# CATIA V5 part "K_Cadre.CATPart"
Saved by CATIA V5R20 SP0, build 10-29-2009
Part number: Cadre
Bounding box of the stored display mesh (mm): x 0 to 570, y 94.924 to 274.924, z -110 to 712.271
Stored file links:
  G:\Khaled_CFAO_2011\ST2M\ST2M_GR1\bmartinez\Khaled\CAD_ThinkMOTION\K_Cadre.CATPart
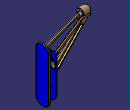
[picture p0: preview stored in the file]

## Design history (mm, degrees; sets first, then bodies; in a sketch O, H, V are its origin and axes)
Body1 (main body)
  Sketch1 on yz-plane, origin (0, 0, 0), H (0, 1, 0), V (0, 0, 1)
    arc A1 centre (187.8381, 667.2714) radius 45 from (227.6929, 646.3767) to (147.9989, 646.3467) ccw
    line L1 (147.9989, 646.3467) -> (110.2498, 449.9415)
    line L2 (110.2498, 449.9415) -> (110.2498, -0.0585)
    arc A2 centre (187.9199, -0.0585) radius 77.6701 from (110.2498, -0.0585) to (265.5899, 0) ccw
    point P5 (265.5899, 0)
    line L3 (265.5899, 0) -> (265.5899, 450)
    line L4 (265.5899, 450) -> (227.6929, 646.3767)
    radius A1 = 45
    distance A1 A2 = 700
    length L3 = 450
    length L2 = 450
    length L4 = 200
    length L1 = 200
    vertical: L2 V, L3 V
    coincidence: P5 H
    tangency: A2 L2
  Pad1: profile Sketch1, direction (1, 0, 0), length 1000
  Sketch2 on zx-plane, origin (0, 0, 0), H (-1, 0, 0), V (0, 0, 1)
    line L1 (40.1591, 586.4466) -> (-1.6835, 586.4466)
    line L2 (-1.6835, 586.4466) -> (-431.6835, -83.5534)
    line L3 (-431.6835, -83.5534) -> (70.1591, -83.5534)
    line L4 (70.1591, -83.5534) -> (40.1591, 586.4466)
    horizontal: L1 H, L3 H
  Pocket1: profile Sketch2, direction (0, -1, 0), length 1000, mirrored extent
  Sketch3 on zx-plane, origin (0, 0, 0), H (-1, 0, 0), V (0, 0, 1)
    line L1 (-100, 740) -> (-100, 650)
    line L2 (-100, 650) -> (-500, 450)
    line L3 (-500, 450) -> (-500, -110)
    line L4 (-500, -110) -> (-1040, -110)
    line L5 (-1040, -110) -> (-1040, 740)
    line L6 (-1040, 740) -> (-100, 740)
    vertical: L1 V, L3 V, L5 V
    horizontal: L4 H, L6 H
  Pocket2: profile Sketch3, direction (0, -1, 0), length 1000, mirrored extent
  Sketch4 on zx-plane, origin (0, 0, 0), H (-1, 0, 0), V (0, 0, 1)
    line L1 (-100, 610) -> (-460, 420)
    line L2 (-460, 420) -> (-460, 250)
    line L3 (-460, 250) -> (-100, 610)
    vertical: L2 V
  Pocket3: profile Sketch4, direction (0, -1, 0), length 1000, mirrored extent
  Sketch5 on zx-plane, origin (0, 0, 0), H (-1, 0, 0), V (0, 0, 1)
    point P1 (0, 600)
    line L1 (0, 600) -> (-450, 130)
    line L2 (-450, 130) -> (-450, -70)
    line L3 (-450, -70) -> (0, -70)
    point P4 (0, -70)
    line L4 (0, -70) -> (0, 600)
    coincidence: P1 V, P4 V
    vertical: L2 V, L4 V
    horizontal: L3 H
  Pocket4: profile Sketch5, direction (0, -1, 0), length 1000, mirrored extent
  Sketch6 on face of Pad1 from Sketch1.L3, origin (0, 265.5899, 0), H (-1, 0, 0), V (0, 0, 1)
    line L1 (-100.3985, 609.6245) -> (0, 609.6245)
    point P2 (0, 609.6245)
    line L2 (0, 609.6245) -> (0, -70)
    line L3 (0, -70) -> (-440, -70)
    line L4 (-440, -70) -> (-460.1088, -70)
    line L5 (-460.1088, -70) -> (-460.1088, 259.8942)
    line L6 (-460.1088, 259.8942) -> (-100.3985, 609.6245)
    coincidence: P2 V
    horizontal: L1 H, L3 H, L4 H
    vertical: L2 V, L5 V
  Pocket5: profile Sketch6, direction (0, -1, 0), length 55
  Sketch7 on face of Pad1 from Sketch1.L2, origin (0, 110.2498, 0), H (1, 0, 0), V (0, 0, 1)
    line L1 (100, 610) -> (460, 250)
    line L2 (460, 250) -> (460, -70)
    line L3 (460, -70) -> (0, -70)
    point P4 (0, -70)
    line L4 (0, -70) -> (0, 610)
    line L5 (0, 610) -> (100, 610)
    vertical: L2 V, L4 V
    coincidence: P4 V
    horizontal: L3 H, L5 H
  Pocket6: profile Sketch7, direction (0, 1, 0), length 55
  Sketch8 on end face of Pocket5, origin (0, 210.5899, 0), H (-1, 0, 0), V (0, 0, 1)
    line L1 (-450, 130) -> (-460, 130)
    line L2 (-460, 130) -> (-460, -100)
    line L3 (-460, -100) -> (-400, -100)
    line L4 (-400, -100) -> (-400, 130)
    line L5 (-400, 130) -> (-450, 130)
    horizontal: L1 H, L3 H, L5 H
    vertical: L2 V, L4 V
  Pocket7: profile Sketch8, direction (0, 1, 0), length 1000, mirrored extent
  Fillet1: radius 15, on edge [end face of Pocket5 | face of Pocket4 from Sketch5.L1]; edge [end face of Pocket5 | face of Pocket3 from Sketch4.L3]; edge [face of Pocket4 from Sketch5.L1 | end face of Pocket6]; edge [face of Pocket3 from Sketch4.L3 | end face of Pocket6]
  Sketch9 on face of Pocket2 from Sketch3.L2, origin (280, 0, 560), H (0, 1, 0), V (-0.8944, 0, 0.4472)
    line L1 (171.5802, 200) -> (199.1817, 200)
    line L2 (199.1817, 200) -> (235.4293, -220)
    line L3 (235.4293, -220) -> (135.4792, -220)
    line L4 (135.4792, -220) -> (171.5802, 200)
    reference projected line E1 (265.5899, -245.9675) -> (227.6929, 193.1442) from edge [face of Pad1 from Sketch1.L4 | face of Pocket2 from Sketch3.L2]
    reference projected line E2 (147.9989, 193.0772) -> (110.261, -245.9675) from edge [face of Pad1 from Sketch1.L1 | face of Pocket2 from Sketch3.L2]
    horizontal: L1 H, L3 H
    parallelism: L2 E1, L4 E2
  Pocket8: profile Sketch9, direction (0.4472, 0, 0.8944), length 45, mirrored extent
  Fillet2: radius 15, on edge [face of Pad1 from Sketch1.L4 | face of Pocket5 from Sketch6.L1]; edge [face of Pocket6 from Sketch7.L5 | face of Pad1 from Sketch1.L1]
  Sketch10 on start face of Pad1, origin (0, 0, 0), H (0, -1, 0), V (0, 0, 1)
    circle A1 centre (-187.8381, 667.2714) radius 25.1
    reference projected arc E1 centre (-187.8381, 667.2714) radius 45 from (-147.9989, 646.3467) to (-227.6929, 646.3767) ccw from edge [start face of Pad1 | face of Pad1 from Sketch1.A1]
    radius A1 = 25.1
    concentricity: A1 E1
  Pocket9: profile Sketch10, direction (1, 0, 0), length 500, mirrored extent
  Sketch11 on face of Pad1 from Sketch1.L2, origin (0, 110.2498, 0), H (1, 0, 0), V (0, 0, 1)
    line L1 (480, 470) -> (480, -110)
    line L2 (480, -110) -> (520, -110)
    line L3 (520, -110) -> (520, 470)
    line L4 (520, 470) -> (480, 470)
    vertical: L1 V, L3 V
    horizontal: L2 H, L4 H
  Pocket10: profile Sketch11, direction (0, 1, 0), length 200
  Fillet3: radius 6, on edge [face of Pad1 from Sketch1.L2 | face of Pocket7]; edge [face of Pad1 from Sketch1.A2 | face of Pocket7]; edge [face of Pocket5 from Sketch6.L5 | face of Pad1 from Sketch1.A2]; edge [face of Pad1 from Sketch1.L3 | face of Pocket5 from Sketch6.L5]; edge [face of Pad1 from Sketch1.L3 | face of Pocket7]
  Fillet4: radius 10, on edge [face of Pocket7 from Sketch8.L1 | face of Pocket4 from Sketch5.L1]; edge [face of Pocket7 from Sketch8.L1 | face of Fillet1] (x2)
  Fillet5: radius 12, on edge [face of Pad1 from Sketch1.L4 | face of Pocket2 from Sketch3.L2]; edge [face of Pad1 from Sketch1.L4 | face of Pocket3 from Sketch4.L1]; edge [face of Pocket3 from Sketch4.L1 | face of Pocket8 from Sketch9.L2]; edge [face of Pocket8 from Sketch9.L2 | face of Pocket2 from Sketch3.L2]; edge [face of Pocket8 from Sketch9.L4 | face of Pocket2 from Sketch3.L2]; edge [face of Pad1 from Sketch1.L1 | face of Pocket2 from Sketch3.L2]; edge [face of Pad1 from Sketch1.L1 | face of Pocket3 from Sketch4.L1]; edge [face of Pocket8 from Sketch9.L4 | face of Pocket3 from Sketch4.L1]
  Fillet6: radius 5, on edge [face of Pocket2 from Sketch3.L2 | face of Pocket8 from Sketch9.L3]
  Fillet7: radius 5, on edge [face of Pad1 from Sketch1.L2 | face of Fillet5]
  Fillet8: radius 5, on edge [face of Pad1 from Sketch1.L3 | face of Fillet5]
  Sketch12 on end face of Pocket6, origin (0, 165.2498, 0), H (1, 0, 0), V (0, 0, 1)
    construction line L1 (100, 550) -> (400, 240)
    line L2 (110.1626, 559.8347) -> (410.1626, 249.8347)
    line L3 (389.8374, 230.1653) -> (89.8374, 540.1653)
    arc A1 centre (400, 240) radius 14.1421 from (410.1626, 249.8347) to (389.8374, 230.1653) cw
    arc A2 centre (100, 550) radius 14.1421 from (89.8374, 540.1653) to (110.1626, 559.8347) cw
    distance L1 L2 = 14.1421
    tangency: A1 L2, A2 L2, A1 L3, A2 L3
  Pocket11: profile Sketch12, direction (0, -1, 0), length 500, mirrored extent
  Sketch13 on face of Pocket10 from Sketch11.L1, origin (480, 0, 0), H (0, 1, 0), V (0, 0, 1)
    circle A1 centre (148.2498, 380) radius 15
    point P1 (148.2498, 380)
    circle A2 centre (227.5899, 380) radius 15
    point P2 (227.5899, 380)
    circle A3 centre (187.9199, 65.4333) radius 25
    point P3 (187.9199, 65.4333)
    reference projected line E1 (112.183, 460) -> (263.6601, 460) from edge [face of Pocket10 from Sketch11.L1 | face of Pocket2 from Sketch3.L2]
    reference projected line E2 (112.183, 460) -> (263.6601, 460) from edge [face of Pocket10 from Sketch11.L1 | face of Pocket2 from Sketch3.L2]
    reference projected line E3 (265.5899, 0) -> (265.5899, 450) from edge [face of Pad1 from Sketch1.L3 | face of Pocket10 from Sketch11.L1]
    reference projected line E4 (110.2498, 449.9415) -> (110.2498, -0.0585) from edge [face of Pad1 from Sketch1.L2 | face of Pocket10 from Sketch11.L1]
    reference projected line E5 (110.2498, 449.9415) -> (110.2498, -0.0585) from edge [face of Pad1 from Sketch1.L2 | face of Pocket10 from Sketch11.L1]
    reference projected line E6 (265.5899, 0) -> (265.5899, 450) from edge [face of Pad1 from Sketch1.L3 | face of Pocket10 from Sketch11.L1]
    reference projected line E7 (265.5899, 0) -> (265.5899, 450) from edge [face of Pad1 from Sketch1.L3 | face of Pocket10 from Sketch11.L1]
    radius A3 = 25
    radius A2 = 15
    radius A1 = 15
    distance P1 E1 = 80
    distance P2 E2 = 80
    distance P2 E3 = 38
    distance E4 P1 = 38
    distance E5 E6 = 155.3402 (reference)
    distance P3 E7 = 77.67
  Pad2: profile Sketch13, direction (1, 0, 0), length 80
  Fillet9: radius 12, on edge [start face of Pad1 | face of Pad1 from Sketch1.L4]; edge [start face of Pad1 | face of Pad1 from Sketch1.A1]; edge [start face of Pad1 | face of Fillet2] (x2); edge [start face of Pad1 | face of Pocket5 from Sketch6.L1]; edge [start face of Pad1 | face of Fillet1] (x2); edge [face of Pocket4 from Sketch5.L1 | start face of Pad1]; edge [start face of Pad1 | face of Pocket6 from Sketch7.L5]; edge [start face of Pad1 | face of Pad1 from Sketch1.L1]
  Chamfer1: length 5, angle 45, on edge [face of Pocket2 from Sketch3.L1 | face of Pad1 from Sketch1.A1]
  Sketch14 on face of Pocket10 from Sketch11.L1, origin (480, 0, 0), H (0, 1, 0), V (0, 0, 1)
    line L1 (120.2498, 357.2843) -> (168.2498, 357.2843)
    line L2 (255.5899, 357.2843) -> (255.5899, 267.2843)
    line L3 (255.5899, 267.2843) -> (120.2498, 267.2843)
    line L4 (120.2498, 267.2843) -> (120.2498, 357.2843)
    reference projected line E1 (265.5899, 0) -> (265.5899, 450) from edge [face of Pad1 from Sketch1.L3 | face of Pocket10 from Sketch11.L1]
    reference projected line E2 (110.2498, 449.9415) -> (110.2498, -0.0585) from edge [face of Pad1 from Sketch1.L2 | face of Pocket10 from Sketch11.L1]
    line L5 (168.2498, 357.2843) -> (168.2498, 447.2843)
    line L6 (168.2498, 447.2843) -> (207.5899, 447.2843)
    line L7 (207.5899, 447.2843) -> (207.5899, 357.2843)
    reference projected circle E3 centre (227.5899, 380) radius 15 from edge [face of Pad2 from Sketch13.A2 | end face of Pad2]
    reference projected circle E4 centre (148.2498, 380) radius 15 from edge [face of Pad2 from Sketch13.A1 | end face of Pad2]
    line L8 (207.5899, 357.2843) -> (255.5899, 357.2843)
    distance L2 E1 = 10
    distance L4 E2 = 10
    distance L1 L3 = 90
    distance E3 L7 = 5
    distance L5 E4 = 5
    angle L8 L7 = 90
    length L7 = 90
    length L5 = 90
    horizontal: L1 H, L3 H, L6 H
    vertical: L2 V, L4 V, L5 V, L7 V
  Pocket12: profile Sketch14, direction (-1, 0, 0), length 30
  Fillet10: radius 20, on edge [face of Pocket12 from Sketch14.L7 | face of Pocket12 from Sketch14.L8]; edge [face of Pocket12 from Sketch14.L1 | face of Pocket12 from Sketch14.L5]
  Chamfer2: length 10, angle 45, on edge [face of Pocket12 from Sketch14.L4 | face of Pocket12 from Sketch14.L1]; edge [face of Pocket12 from Sketch14.L8 | face of Pocket12 from Sketch14.L2]; edge [face of Pocket12 from Sketch14.L2 | face of Pocket12 from Sketch14.L3]; edge [face of Pocket12 from Sketch14.L3 | face of Pocket12 from Sketch14.L4]
  Chamfer3: length 5, angle 45, on edge [face of Pocket7 | face of Fillet10] (x2); edge [face of Pocket7 | face of Pocket12 from Sketch14.L1]; edge [face of Chamfer2 | face of Pocket7] (x4); edge [face of Pocket12 from Sketch14.L4 | face of Pocket7]; edge [face of Pocket7 | face of Pocket12 from Sketch14.L3]; edge [face of Pocket12 from Sketch14.L2 | face of Pocket7]; edge [face of Pocket7 | face of Pocket12 from Sketch14.L8]; edge [face of Pocket7 | face of Pocket12 from Sketch14.L7]; edge [face of Pocket12 from Sketch14.L5 | face of Pocket7]
  Sketch15 on end face of Pad2, origin (560, 0, 0), H (0, 1, 0), V (0, 0, 1)
    circle A1 centre (187.9199, 65.4333) radius 20
    reference projected circle E1 centre (187.9199, 65.4333) radius 25 from edge [face of Pad2 from Sketch13.A3 | end face of Pad2]
    circle A2 centre (227.5899, 380) radius 12.5
    reference projected circle E2 centre (227.5899, 380) radius 15 from edge [face of Pad2 from Sketch13.A2 | end face of Pad2]
    circle A3 centre (148.2498, 380) radius 12.5
    reference projected circle E3 centre (148.2498, 380) radius 15 from edge [face of Pad2 from Sketch13.A1 | end face of Pad2]
    radius A1 = 20
    radius A2 = 12.5
    radius A3 = 12.5
    concentricity: A1 E1, A2 E2, A3 E3
  Pocket13: profile Sketch15, direction (-1, 0, 0), length 60
  Sketch16 on end face of Pad2, origin (560, 0, 0), H (0, 1, 0), V (0, 0, 1)
    line L1 (94.9242, 570) -> (274.9242, 570)
    line L2 (274.9242, 570) -> (274.9242, -110)
    line L3 (274.9242, -110) -> (94.9242, -110)
    line L4 (94.9242, -110) -> (94.9242, 570)
    horizontal: L1 H, L3 H
    vertical: L2 V, L4 V
  Pad3: profile Sketch16, direction (1, 0, 0), length 10
  Fillet11: radius 80, on edge [face of Pad3 from Sketch16.L3 | face of Pad3 from Sketch16.L4]; edge [face of Pad3 from Sketch16.L2 | face of Pad3 from Sketch16.L3]
  Fillet12: radius 90, on edge [face of Pad3 from Sketch16.L1 | face of Pad3 from Sketch16.L2]; edge [face of Pad3 from Sketch16.L4 | face of Pad3 from Sketch16.L1]
  Chamfer4: length 9, angle 45, on edge [end face of Pad3 | face of Fillet12] (x2)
